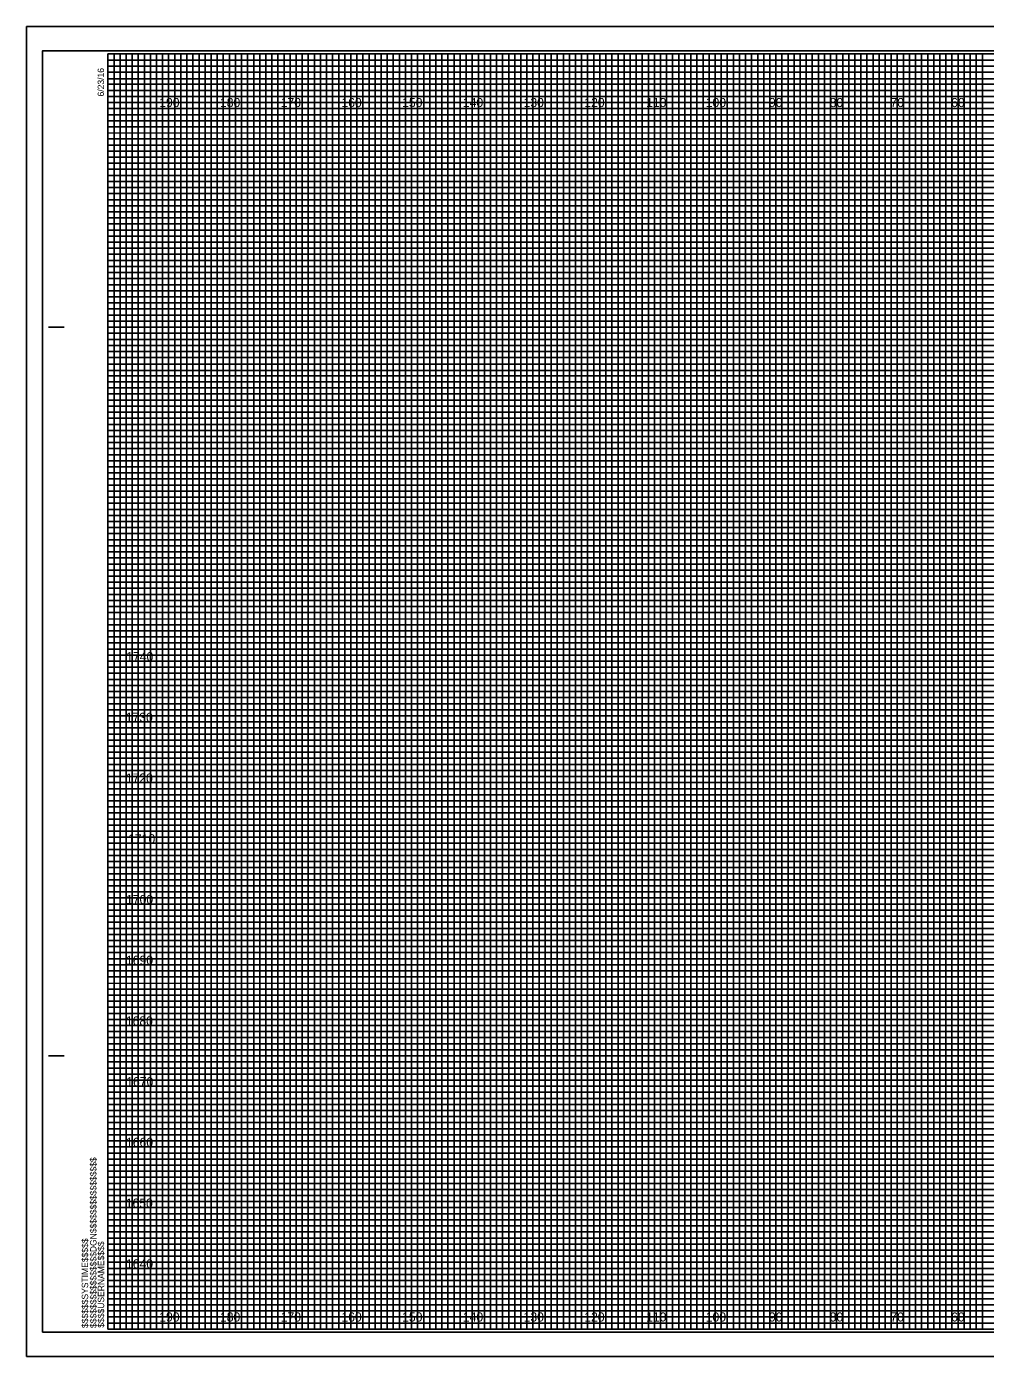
# Model space of a CAD drawing. Extents: x -13 to 323, y -5 to 6154.
# Drawn here: x -13.4 to 144.5, y 656 to 875 of the extents above; entities that cross this region are included whole.
import ezdxf

# ---------------------------------------------------------------- set-up
doc = ezdxf.new("R2010")
doc.units = 0
for name, color, linetype in [('Prop Retaining Wall', 7, 'Continuous'), ('Prop XS Alignment Label', 7, 'Continuous'), ('Prop XS DDE', 7, 'Continuous'), ('Prop XS DDE Elevations', 7, 'Continuous'), ('Prop XS DDE Slope Text', 7, 'Continuous'), ('Prop XS Earthwork Shape', 7, 'Continuous'), ('Prop XS Elevation Labels', 7, 'Continuous'), ('Prop XS Station Labels', 7, 'Continuous'), ('Raster_Level_0', 7, 'Continuous'), ('Scratch_Level_3', 7, 'Continuous'), ('Sheet Cutting Line CELL', 7, 'Continuous')]:
    doc.layers.add(name, color=color, linetype=linetype)

msp = doc.modelspace()

# ---------------------------------------------------------------- linework, layer by layer
at = {"layer": 'Prop Retaining Wall'}
for p, q in [((-0.04, 869.45), (259.96, 869.45)), ((259.96, 868.43), (-0.04, 868.43)), ((-0.04, 868.43), (-0.04, 867.45)), ((-0.04, 867.45), (259.96, 867.45)), ((259.96, 866.34), (-0.04, 866.34)), ((-0.04, 866.34), (-0.04, 864.45)), ((-0.04, 864.45), (319.96, 864.45))]:
    msp.add_line(p, q, dxfattribs=at)
for points in [[(-0.04, 863.45), (269.96, 863.45), (319.96, 863.45), (319.96, 862.45), (-0.04, 862.45)], [(-0.04, 861.45), (319.96, 861.45), (319.96, 859.45), (-0.04, 859.45)], [(-0.04, 858.45), (319.96, 858.45), (319.96, 857.45), (-0.04, 857.43)], [(-0.04, 856.45), (319.96, 856.45), (319.96, 854.45), (-0.04, 854.45)], [(-0.04, 853.45), (319.96, 853.45), (319.96, 852.45), (-0.04, 852.45)], [(-0.04, 851.45), (319.96, 851.45), (319.96, 849.45), (-0.04, 849.45)], [(-0.04, 848.45), (319.96, 848.45), (319.96, 847.45), (-0.04, 847.45)], [(-0.04, 846.45), (319.96, 846.45), (319.96, 844.45), (-0.04, 844.45)], [(-0.04, 843.45), (319.96, 843.45), (319.96, 842.45), (-0.04, 842.45)], [(-0.04, 841.45), (319.96, 841.45), (319.96, 839.45), (-0.04, 839.45)], [(-0.04, 838.45), (319.96, 838.45), (319.96, 837.45), (-0.04, 837.45)], [(-0.04, 836.45), (319.96, 836.45), (319.96, 834.4), (319.96, 833.45), (319.96, 832.45), (-0.04, 832.45)], [(-0.04, 834.45), (319.96, 834.45), (319.96, 833.45), (-0.04, 833.45)], [(-0.04, 831.45), (319.96, 831.45), (319.96, 829.45), (-0.04, 829.48)], [(-0.04, 829.48), (319.96, 829.45), (319.96, 828.45), (-0.04, 828.45)], [(-0.04, 827.45), (319.96, 827.45), (319.96, 826.45), (-0.04, 826.45)], [(-0.04, 824.45), (319.96, 824.45), (319.96, 823.45), (-0.04, 823.45)], [(-0.04, 822.45), (319.96, 822.45), (319.96, 821.45), (-0.04, 821.45)], [(-0.11, 819.34), (319.96, 819.34), (319.96, 818.33), (-0.11, 818.33)], [(-0.04, 817.45), (319.96, 817.45), (319.96, 816.45), (-0.04, 816.45)], [(-0.04, 814.45), (319.96, 814.45), (319.96, 813.45), (-0.04, 813.45)], [(-0.04, 812.45), (319.96, 812.45), (319.96, 811.45), (-0.04, 811.45)], [(-0.04, 809.45), (319.96, 809.45), (319.96, 808.45), (-0.04, 808.45)], [(-0.04, 807.45), (319.96, 807.45), (319.96, 806.45), (-0.04, 806.45)], [(-0.04, 804.45), (319.96, 804.45), (319.96, 803.45), (-0.04, 803.45)], [(-0.04, 802.45), (319.96, 802.45), (319.96, 801.45), (-0.04, 801.45)], [(-0.04, 799.45), (319.96, 799.45), (319.95, 798.43), (-0.04, 798.45)], [(-0.04, 797.45), (319.96, 797.45), (319.96, 796.45), (-0.04, 796.45)], [(-0.04, 794.45), (319.96, 794.45), (319.96, 793.45), (-0.04, 793.45)], [(-0.04, 792.45), (319.96, 792.45), (319.96, 791.45), (-0.04, 791.45)], [(-0.04, 789.45), (319.96, 789.45), (319.96, 788.45), (-0.04, 788.45)], [(-0.04, 787.45), (319.96, 787.45), (319.96, 786.45), (-0.04, 786.45)], [(-0.04, 784.45), (319.96, 784.45), (319.96, 783.45), (-0.04, 783.45)], [(-0.04, 782.45), (319.96, 782.45), (319.96, 781.45), (-0.04, 781.45)], [(-0.04, 779.45), (319.96, 779.45), (319.96, 778.45), (-0.04, 778.45)], [(-0.04, 777.44), (320.03, 777.36), (319.96, 776.45), (-0.04, 776.45)], [(-0.04, 774.45), (319.96, 774.45), (319.96, 773.45), (-0.04, 773.45)], [(-0.04, 772.45), (319.96, 772.45), (319.96, 771.45), (-0.04, 771.45)], [(-0.04, 769.45), (319.96, 769.45), (319.96, 768.45), (-0.04, 768.45)], [(-0.04, 767.45), (319.96, 767.45), (319.96, 766.45), (-0.04, 766.45)], [(-0.04, 764.45), (319.96, 764.45), (319.96, 763.45), (-0.04, 763.45)], [(-0.04, 762.45), (319.96, 762.45), (319.96, 761.45), (-0.04, 761.45)], [(-0.04, 759.45), (319.96, 759.45), (319.96, 758.45), (-0.04, 758.45)], [(-0.04, 757.45), (319.96, 757.45), (319.96, 756.45), (-0.04, 756.45)], [(-0.04, 754.45), (319.96, 754.45), (319.96, 753.45), (-0.04, 753.45)], [(-0.04, 752.45), (319.96, 752.45), (319.96, 751.45), (-0.04, 751.45)], [(-0.04, 749.45), (319.96, 749.45), (319.96, 748.45), (-0.04, 748.45)], [(-0.04, 747.45), (319.96, 747.45), (319.96, 746.45), (-0.04, 746.45)], [(-0.04, 744.45), (319.96, 744.45), (319.96, 743.45), (-0.04, 743.45)], [(-0.04, 742.45), (319.96, 742.45), (319.96, 741.45), (-0.04, 741.45)], [(-0.04, 739.45), (319.96, 739.45), (319.95, 738.43), (-0.04, 738.45)], [(-0.04, 737.45), (319.96, 737.45), (319.96, 736.45), (-0.04, 736.45)], [(-0.04, 734.45), (319.96, 734.45), (319.96, 733.45), (-0.04, 733.45)], [(-0.04, 732.45), (319.96, 732.45), (319.96, 731.45), (-0.04, 731.45)], [(-0.04, 729.45), (319.96, 729.45), (319.96, 728.45), (-0.04, 728.45)], [(-0.04, 727.45), (319.96, 727.45), (319.96, 726.45), (-0.04, 726.45)], [(-0.04, 724.45), (319.96, 724.45), (319.96, 723.45), (-0.04, 723.45)], [(-0.04, 722.45), (319.96, 722.45), (319.96, 721.45), (-0.04, 721.45)], [(-0.04, 719.45), (319.96, 719.45), (319.96, 718.45), (-0.04, 718.45)], [(-0.04, 717.44), (320.03, 717.36), (319.96, 716.45), (-0.04, 716.45)], [(-0.04, 714.45), (319.96, 714.45), (319.96, 713.45), (-0.04, 713.45)], [(-0.04, 712.45), (319.96, 712.45), (319.96, 711.45), (-0.04, 711.45)], [(-0.04, 709.45), (319.96, 709.45), (319.96, 708.45), (-0.04, 708.45)], [(-0.04, 707.45), (319.96, 707.45), (319.96, 706.45), (-0.04, 706.45)], [(-0.04, 704.45), (319.96, 704.45), (319.96, 703.45), (-0.04, 703.45)], [(-0.04, 702.45), (319.96, 702.45), (319.96, 701.45), (-0.04, 701.45)], [(-0.04, 699.45), (319.96, 699.45), (319.96, 698.45), (-0.04, 698.45)], [(-0.04, 697.45), (319.96, 697.45), (319.96, 696.45), (-0.04, 696.45)], [(-0.04, 694.45), (319.96, 694.45), (319.96, 693.45), (-0.04, 693.45)], [(-0.04, 692.45), (319.96, 692.45), (319.96, 691.45), (-0.04, 691.45)], [(-0.04, 689.45), (319.96, 689.45), (319.96, 688.45), (-0.04, 688.45)], [(-0.04, 687.45), (319.96, 687.45), (319.96, 686.45), (-0.04, 686.45)], [(-0.04, 684.45), (319.96, 684.45), (319.96, 683.45), (-0.04, 683.45)], [(-0.04, 682.45), (319.96, 682.45), (319.96, 681.45), (-0.04, 681.45)], [(-0.04, 679.45), (319.96, 679.45), (319.96, 678.45), (-0.04, 678.45)], [(-0.04, 677.45), (319.96, 677.45), (319.96, 676.45), (-0.04, 676.45)], [(-0.04, 674.45), (319.96, 674.45), (319.96, 673.45), (-0.04, 673.45)], [(-0.04, 672.45), (319.96, 672.45), (319.96, 671.45), (-0.04, 671.45)], [(-0.04, 669.45), (319.96, 669.45), (319.96, 668.45), (-0.04, 668.45)], [(-0.04, 667.45), (319.96, 667.45), (319.96, 666.45), (-0.04, 666.45)], [(-0.04, 664.45), (319.96, 664.45), (319.96, 663.45), (-0.04, 663.45)], [(-0.04, 662.45), (319.96, 662.45), (319.96, 661.45), (-0.04, 661.45)]]:
    msp.add_lwpolyline(points, dxfattribs=at)
at = {"layer": 'Prop XS Alignment Label'}
for p, q in [((-9.84, 825.45), (-7.34, 825.45)), ((-9.74, 825.45), (-7.24, 825.45)), ((-9.84, 705.45), (-7.34, 705.45)), ((-9.74, 705.45), (-7.24, 705.45)), ((-0.04, 660.45), (-0.04, 660.45)), ((-0.04, 660.45), (-0.04, 660.45)), ((-0.04, 660.45), (-0.04, 660.45)), ((-0.04, 660.45), (-0.04, 660.45)), ((-0.04, 660.45), (-0.04, 660.45)), ((-0.04, 660.45), (-0.04, 660.45)), ((-0.04, 660.45), (-0.04, 660.45))]:
    msp.add_line(p, q, dxfattribs=at)
msp.add_lwpolyline([(319.96, 870.45), (-0.04, 870.45), (-0.04, 660.45), (319.96, 660.45)], close=True, dxfattribs=at)
at = {"layer": 'Prop XS DDE'}
msp.add_lwpolyline([(-13.44, 655.95), (323.26, 655.95), (323.26, 874.95), (-13.44, 874.95)], close=True, dxfattribs=at)
at = {"layer": 'Prop XS DDE Elevations'}
for p, q in [((9.96, 660.45), (9.96, 870.45)), ((19.96, 660.45), (19.96, 870.45)), ((29.96, 660.45), (29.96, 870.45)), ((39.96, 660.45), (39.96, 870.45)), ((49.96, 660.45), (49.96, 870.45)), ((59.96, 660.45), (59.96, 870.45)), ((69.96, 660.45), (69.96, 870.45)), ((79.96, 660.45), (79.96, 870.45)), ((89.96, 660.45), (89.96, 870.45)), ((99.96, 660.45), (99.96, 870.45)), ((109.96, 660.45), (109.96, 870.45)), ((119.96, 660.45), (119.96, 870.45)), ((129.96, 660.45), (129.96, 870.45)), ((139.96, 660.45), (139.96, 870.45)), ((-0.04, 860.45), (319.96, 860.45)), ((-0.04, 850.45), (319.96, 850.45)), ((-0.04, 840.45), (319.96, 840.45)), ((-0.04, 830.45), (319.96, 830.45)), ((-0.04, 820.45), (319.96, 820.45)), ((-0.04, 810.45), (319.96, 810.45)), ((-0.04, 800.45), (319.96, 800.45)), ((-0.04, 790.45), (319.96, 790.45)), ((-0.04, 780.45), (319.96, 780.45)), ((-0.04, 770.45), (319.96, 770.45)), ((-0.04, 760.45), (319.96, 760.45)), ((-0.04, 750.45), (319.96, 750.45)), ((-0.04, 740.45), (319.96, 740.45)), ((-0.04, 730.45), (319.96, 730.45)), ((-0.04, 720.45), (319.96, 720.45)), ((-0.04, 710.45), (319.96, 710.45)), ((-0.04, 700.45), (319.96, 700.45)), ((-0.04, 690.45), (319.96, 690.45)), ((-0.04, 680.45), (319.96, 680.45)), ((-0.04, 670.45), (319.96, 670.45))]:
    msp.add_line(p, q, dxfattribs=at)
at = {"layer": 'Prop XS DDE Slope Text'}
msp.add_lwpolyline([(-10.84, 659.95), (322.36, 659.95), (322.36, 870.95), (-10.84, 870.95)], close=True, dxfattribs=at)
at = {"layer": 'Prop XS Earthwork Shape'}
for p, q in [((9.96, 870.45), (-0.04, 870.45)), ((9.96, 660.45), (9.96, 870.45)), ((29.96, 870.45), (19.96, 870.45)), ((19.96, 870.45), (19.96, 660.45)), ((29.96, 660.45), (29.96, 870.45)), ((49.96, 870.45), (39.96, 870.45)), ((39.96, 870.45), (39.96, 660.45)), ((49.96, 660.45), (49.96, 870.45)), ((69.96, 870.45), (59.96, 870.45)), ((59.96, 870.45), (59.96, 660.45)), ((69.96, 660.45), (69.96, 870.45)), ((89.96, 870.45), (79.96, 870.45)), ((79.96, 870.45), (79.96, 660.45)), ((89.96, 660.45), (89.96, 870.45)), ((109.96, 870.45), (99.96, 870.45)), ((99.96, 870.45), (99.96, 660.45)), ((109.96, 660.45), (109.96, 870.45)), ((129.96, 870.45), (119.96, 870.45)), ((119.96, 870.45), (119.96, 660.45)), ((129.96, 660.45), (129.96, 870.45)), ((149.96, 870.45), (139.96, 870.45)), ((139.96, 870.45), (139.96, 660.45)), ((19.96, 660.45), (9.96, 660.45)), ((39.96, 660.45), (29.96, 660.45)), ((59.96, 660.45), (49.96, 660.45)), ((79.96, 660.45), (69.96, 660.45)), ((99.96, 660.45), (89.96, 660.45)), ((119.96, 660.45), (109.96, 660.45)), ((139.96, 660.45), (129.96, 660.45))]:
    msp.add_line(p, q, dxfattribs=at)
for points in [[(-0.04, 860.45), (319.96, 860.45), (319.96, 850.45), (-0.04, 850.45)], [(-0.04, 840.45), (319.96, 840.45), (319.96, 830.45), (-0.04, 830.45)], [(-0.04, 820.45), (319.96, 820.45), (319.96, 810.45), (-0.04, 810.45)], [(-0.04, 800.45), (319.96, 800.45), (319.96, 790.45), (-0.04, 790.45)], [(-0.04, 780.45), (319.96, 780.45), (319.96, 770.45), (-0.04, 770.45)], [(-0.04, 760.45), (319.96, 760.45), (319.96, 750.45), (-0.04, 750.45)], [(-0.04, 740.45), (319.96, 740.45), (319.96, 730.45), (-0.04, 730.45)], [(-0.04, 720.45), (319.96, 720.45), (319.96, 710.45), (-0.04, 710.45)], [(-0.04, 700.45), (319.96, 700.45), (319.96, 690.45), (-0.04, 690.45)], [(-0.04, 680.45), (319.96, 680.45), (319.96, 670.45), (-0.04, 670.45)]]:
    msp.add_lwpolyline(points, dxfattribs=at)
at = {"layer": 'Prop XS Elevation Labels'}
for points in [[(-0.04, 660.45), (0.96, 660.45), (0.96, 870.45), (1.96, 870.45), (1.96, 660.45)], [(1.96, 660.45), (2.96, 660.45), (2.96, 870.45), (3.96, 870.45), (3.96, 660.45)], [(4.96, 660.45), (5.96, 660.45), (5.96, 870.45), (6.96, 870.45), (6.96, 660.45)], [(6.96, 660.45), (7.96, 660.45), (7.96, 870.45), (8.96, 870.45), (8.96, 660.45)], [(9.96, 660.45), (10.96, 660.45), (10.96, 870.45), (11.96, 870.45), (11.96, 660.45)], [(11.96, 660.45), (12.96, 660.45), (12.96, 870.45), (13.96, 870.45), (13.96, 660.45)], [(14.96, 660.45), (15.96, 660.45), (15.96, 870.45), (16.96, 870.45), (16.96, 660.45)], [(16.96, 660.45), (17.96, 660.45), (17.96, 870.45), (18.96, 870.45), (18.96, 660.45)], [(19.96, 660.45), (20.96, 660.45), (20.96, 870.45), (21.96, 870.45), (21.96, 660.45)], [(21.96, 660.45), (22.96, 660.45), (22.96, 870.45), (23.96, 870.45), (23.96, 660.45)], [(24.96, 660.45), (25.96, 660.45), (25.96, 870.45), (26.96, 870.45), (26.96, 660.45)], [(26.96, 660.45), (27.96, 660.45), (27.96, 870.45), (28.96, 870.45), (28.96, 660.45)], [(29.96, 660.45), (30.96, 660.45), (30.96, 870.45), (31.96, 870.45), (31.96, 660.45)], [(31.96, 660.45), (32.96, 660.45), (32.96, 870.45), (33.96, 870.45), (33.96, 660.45)], [(34.96, 660.45), (35.96, 660.45), (35.96, 870.45), (36.96, 870.45), (36.96, 660.45)], [(36.96, 660.45), (37.96, 660.45), (37.96, 870.45), (38.96, 870.45), (38.96, 660.45)], [(39.96, 660.45), (40.96, 660.45), (40.96, 870.45), (41.96, 870.45), (41.96, 660.45)], [(41.96, 660.45), (42.96, 660.45), (42.96, 870.45), (43.96, 870.45), (43.96, 660.45)], [(44.96, 660.45), (45.96, 660.45), (45.96, 870.45), (46.96, 870.45), (46.96, 660.45)], [(46.96, 660.45), (47.96, 660.45), (47.96, 870.45), (48.96, 870.45), (48.96, 660.45)], [(49.96, 660.45), (50.96, 660.45), (50.96, 870.45), (51.96, 870.45), (51.96, 660.45)], [(51.96, 660.45), (52.96, 660.45), (52.96, 870.45), (53.96, 870.45), (53.96, 660.45)], [(54.96, 660.45), (55.96, 660.45), (55.96, 870.45), (56.96, 870.45), (56.96, 660.45)], [(56.96, 660.45), (57.96, 660.45), (57.96, 870.45), (58.96, 870.45), (58.96, 660.45)], [(59.96, 660.45), (60.96, 660.45), (60.96, 870.45), (61.96, 870.45), (61.96, 660.45)], [(61.96, 660.45), (62.96, 660.45), (62.96, 870.45), (63.96, 870.45), (63.96, 660.45)], [(64.96, 660.45), (65.96, 660.45), (65.96, 870.45), (66.96, 870.45), (66.96, 660.45)], [(66.96, 660.45), (67.96, 660.45), (67.96, 870.45), (68.96, 870.45), (68.96, 660.45)], [(69.96, 660.45), (70.96, 660.45), (70.96, 870.45), (71.96, 870.45), (71.96, 660.45)], [(71.96, 660.45), (72.96, 660.45), (72.96, 870.45), (73.96, 870.45), (73.96, 660.45)], [(74.96, 660.45), (75.96, 660.45), (75.96, 870.45), (76.96, 870.45), (76.96, 660.45)], [(76.96, 660.45), (77.96, 660.45), (77.96, 870.45), (78.96, 870.45), (78.96, 660.45)], [(79.96, 660.45), (80.96, 660.45), (80.96, 870.45), (81.96, 870.45), (81.96, 660.45)], [(81.96, 660.45), (82.96, 660.45), (82.96, 870.45), (83.96, 870.45), (83.96, 660.45)], [(84.96, 660.45), (85.96, 660.45), (85.96, 870.45), (86.96, 870.45), (86.96, 660.45)], [(86.96, 660.45), (87.96, 660.45), (87.96, 870.45), (88.96, 870.45), (88.96, 660.45)], [(89.96, 660.45), (90.96, 660.45), (90.96, 870.45), (91.96, 870.45), (91.96, 660.45)], [(91.96, 660.45), (92.96, 660.45), (92.96, 870.45), (93.96, 870.45), (93.96, 660.45)], [(94.96, 660.45), (95.96, 660.45), (95.96, 870.45), (96.96, 870.45), (96.96, 660.45)], [(96.96, 660.45), (97.96, 660.45), (97.96, 870.45), (98.96, 870.45), (98.96, 660.45)], [(99.96, 660.45), (100.96, 660.45), (100.96, 870.45), (101.96, 870.45), (101.96, 660.45)], [(101.96, 660.45), (102.96, 660.45), (102.96, 870.45), (103.96, 870.45), (103.96, 660.45)], [(104.96, 660.45), (105.96, 660.45), (105.96, 870.45), (106.96, 870.45), (106.96, 660.45)], [(106.96, 660.45), (107.96, 660.45), (107.96, 870.45), (108.96, 870.45), (108.96, 660.45)], [(109.96, 660.45), (110.96, 660.45), (110.96, 870.45), (111.96, 870.45), (111.96, 660.45)], [(111.96, 660.45), (112.96, 660.45), (112.96, 870.45), (113.96, 870.45), (113.96, 660.45)], [(114.96, 660.45), (115.96, 660.45), (115.96, 870.45), (116.96, 870.45), (116.96, 660.45)], [(116.96, 660.45), (117.96, 660.45), (117.96, 870.45), (118.96, 870.45), (118.96, 660.45)], [(119.96, 660.45), (120.96, 660.45), (120.96, 870.45), (121.96, 870.45), (121.96, 660.45)], [(121.96, 660.45), (122.96, 660.45), (122.96, 870.45), (123.96, 870.45), (123.96, 660.45)], [(124.96, 660.45), (125.96, 660.45), (125.96, 870.45), (126.96, 870.45), (126.96, 660.45)], [(126.96, 660.45), (127.96, 660.45), (127.96, 870.45), (128.96, 870.45), (128.96, 660.45)], [(129.96, 660.45), (130.96, 660.45), (130.96, 870.45), (131.96, 870.45), (131.96, 660.45)], [(131.96, 660.45), (132.96, 660.45), (132.96, 870.45), (133.96, 870.45), (133.96, 660.45)], [(134.96, 660.45), (135.96, 660.45), (135.96, 870.45), (136.96, 870.45), (136.96, 660.45)], [(136.96, 660.45), (137.96, 660.45), (137.96, 870.45), (138.96, 870.45), (138.96, 660.45)], [(139.96, 660.45), (140.96, 660.45), (140.96, 870.45), (141.96, 870.45), (141.96, 660.45)], [(141.96, 660.45), (142.96, 660.45), (142.96, 870.45), (143.96, 870.45), (143.96, 660.45)]]:
    msp.add_lwpolyline(points, dxfattribs=at)
at = {"layer": 'Prop XS Station Labels'}
for points in [[(-0.04, 870.45), (4.96, 870.45), (4.96, 660.45), (14.96, 660.45), (14.96, 870.45), (24.96, 870.45), (24.96, 660.45), (34.96, 660.45), (34.96, 870.45), (44.96, 870.45), (44.96, 660.45), (54.96, 660.45), (54.96, 870.45), (64.96, 870.45), (64.96, 660.45), (74.96, 660.45), (74.96, 870.45), (84.96, 870.45), (84.96, 660.45), (94.96, 660.45), (94.96, 870.45), (104.96, 870.45), (104.96, 660.45), (114.96, 660.45), (114.96, 870.45), (124.96, 870.45), (124.96, 660.45), (134.96, 660.45), (134.96, 870.45), (144.96, 870.45)], [(-0.04, 865.45), (274.96, 865.45)], [(-0.04, 845.45), (319.96, 845.45), (319.96, 855.45), (-0.04, 855.45)], [(-0.04, 825.45), (319.96, 825.45), (319.96, 835.45), (-0.04, 835.45)], [(-0.04, 805.45), (319.96, 805.45), (319.96, 815.45), (-0.04, 815.45)], [(-0.04, 785.45), (319.96, 785.45), (319.96, 795.45), (-0.04, 795.45)], [(-0.04, 765.45), (319.96, 765.45), (319.96, 775.45), (-0.04, 775.45)], [(-0.04, 745.45), (319.96, 745.45), (319.96, 755.45), (-0.04, 755.45)], [(-0.04, 725.45), (319.96, 725.45), (319.96, 735.45), (-0.04, 735.45)], [(-0.04, 705.45), (319.96, 705.45), (319.96, 715.45), (-0.04, 715.45)], [(-0.04, 685.45), (319.96, 685.45), (319.96, 695.45), (-0.04, 695.45)], [(-0.04, 665.45), (319.96, 665.45), (319.96, 675.45), (-0.04, 675.45)]]:
    msp.add_lwpolyline(points, dxfattribs=at)
at = {"layer": 'Sheet Cutting Line CELL'}
for p, q in [((323.26, 874.95), (-13.44, 874.95)), ((-13.44, 874.95), (-13.44, 655.95)), ((-13.44, 655.95), (323.26, 655.95))]:
    msp.add_line(p, q, dxfattribs=at)

# ---------------------------------------------------------------- texts
at = {"layer": 'Prop XS Alignment Label'}
for s, p in [('6/23/16', (-0.69, 863.45)), ('$$$$$$$$$$$$$$$$DGN$$$$$$$$$$$$$$$$', (-1.92, 660.63)), ('$$$$$$SYSTIME$$$$$', (-3.3, 660.63)), ('$$$$USERNAME$$$$', (-0.66, 660.68))]:
    msp.add_text(s, height=1.05, rotation=90, dxfattribs=at).set_placement(p)
at = {"layer": 'Raster_Level_0'}
for s, p in [('190', (8.41, 861.7)), ('180', (18.41, 861.7)), ('170', (28.41, 861.7)), ('160', (38.41, 861.7)), ('150', (48.41, 861.7)), ('140', (58.41, 861.7)), ('130', (68.41, 861.7)), ('120', (78.41, 861.7)), ('110', (88.59, 861.7)), ('100', (98.41, 861.7)), ('90', (108.82, 861.7)), ('80', (118.82, 861.7)), ('70', (128.82, 861.7)), ('60', (138.82, 861.7)), ('190', (8.41, 661.7)), ('180', (18.41, 661.7)), ('170', (28.41, 661.7)), ('160', (38.41, 661.7)), ('150', (48.41, 661.7)), ('140', (58.41, 661.7)), ('130', (68.41, 661.7)), ('120', (78.41, 661.7)), ('110', (88.59, 661.7)), ('100', (98.41, 661.7)), ('90', (108.82, 661.7)), ('80', (118.82, 661.7)), ('70', (128.82, 661.7)), ('60', (138.82, 661.7))]:
    msp.add_text(s, height=1.5, dxfattribs=at).set_placement(p)
at = {"layer": 'Scratch_Level_3'}
for s, p in [('1740', (2.97, 770.45)), ('1730', (2.89, 760.45)), ('1720', (2.9, 750.45)), ('1710', (3.28, 740.45)), ('1700', (2.94, 730.45)), ('1690', (2.93, 720.45)), ('1680', (2.91, 710.45)), ('1670', (2.97, 700.45)), ('1660', (2.93, 690.45)), ('1650', (2.89, 680.45)), ('1640', (2.93, 670.45))]:
    msp.add_text(s, height=1.5, dxfattribs=at).set_placement(p)

doc.saveas('drawing.dxf')
